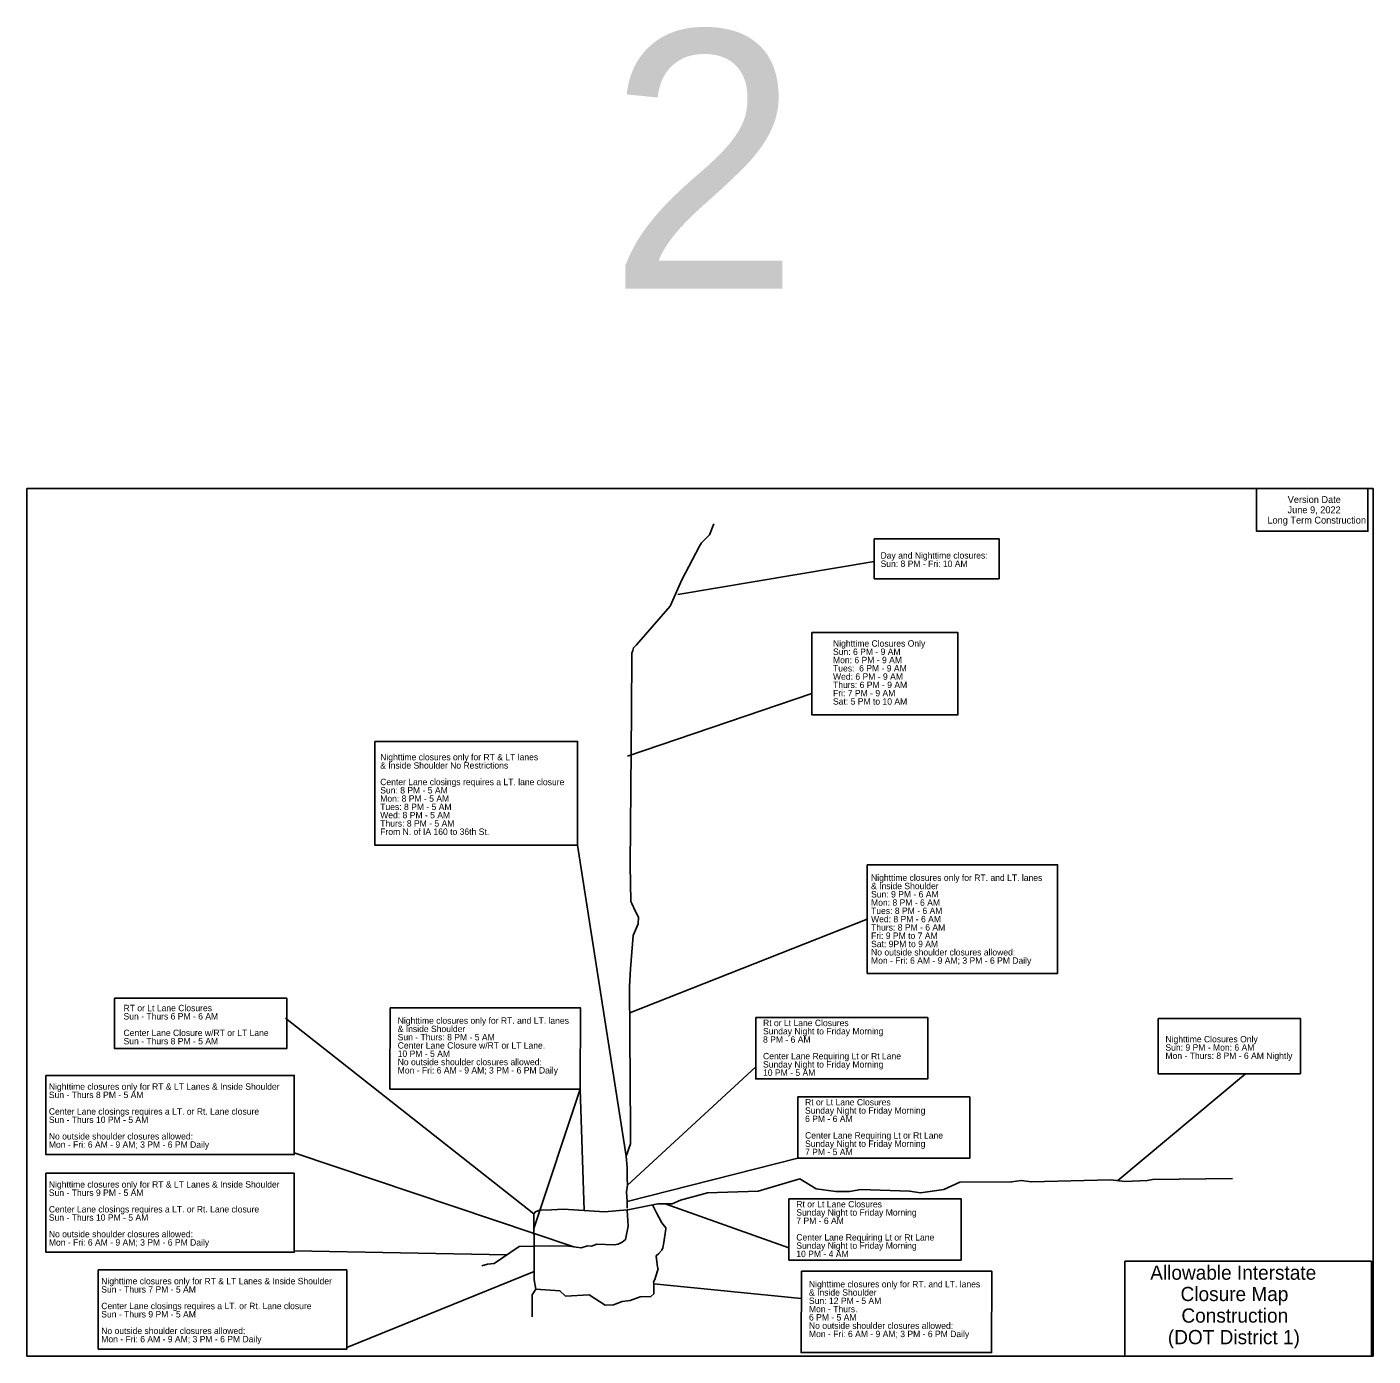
# Model space of a CAD drawing. Extents: x 10133 to 81668, y 7924 to 11018.
# Drawn here: x 13733 to 16868, y 7924 to 11018 of the extents above; entities that cross this region are included whole.
import ezdxf

# ---------------------------------------------------------------- set-up
doc = ezdxf.new("R2010")
doc.units = 0
for name, color, linetype in [('Level 1', 7, 'Continuous'), ('Level 10', 7, 'Continuous'), ('Level 12', 7, 'Continuous'), ('Level 4', 7, 'Continuous'), ('Level 5', 7, 'Continuous'), ('Level 6', 7, 'Continuous'), ('Level 63', 7, 'Continuous'), ('Level 7', 7, 'Continuous'), ('SheetAddendum', 7, 'Continuous'), ('SheetBorder', 7, 'Continuous'), ('SheetText', 7, 'Continuous')]:
    doc.layers.add(name, color=color, linetype=linetype)

msp = doc.modelspace()

# ---------------------------------------------------------------- linework, layer by layer
at = {"layer": 'Level 1'}
for p, q in [((16289.1, 8145), (16863.6, 8145)), ((16863.6, 8145), (16863.6, 7924)), ((16863.6, 7924), (16289.1, 7924))]:
    msp.add_line(p, q, dxfattribs=at)
msp.add_lwpolyline([(16289.1, 7924), (16289.1, 7924), (16289.1, 8145)], dxfattribs=at)
at = {"layer": 'Level 10'}
msp.add_line((15015, 9113.4), (15128.1, 8389.4), dxfattribs=at)
msp.add_lwpolyline([(14542.4, 9354.9), (15015, 9354.9), (15015, 9113.4), (14542.4, 9113.4)], close=True, dxfattribs=at)
for points in [[(15138.3, 8451.6), (15138.5, 8422.8), (15138.5, 8417.9), (15128.1, 8389.4)], [(15128.1, 8389.4), (15130.6, 8363.2), (15130.2, 8338.5)]]:
    msp.add_lwpolyline(points, dxfattribs=at)
at = {"layer": 'Level 12'}
msp.add_lwpolyline([(16596.1, 9944), (16855.7, 9944), (16855.7, 9844), (16596.1, 9844)], close=True, dxfattribs=at)
at = {"layer": 'Level 4'}
for p, q in [((15689.4, 8941.2), (15136.4, 8722.9)), ((15535.6, 8058.4), (15192.2, 8091.8))]:
    msp.add_line(p, q, dxfattribs=at)
for points in [[(15689.4, 9067.6), (16132.9, 9067.6), (16132.9, 8814.7), (15689.4, 8814.7)], [(15536.2, 8121.3), (15979.6, 8121.3), (15979.1, 7932), (15535.6, 7932)]]:
    msp.add_lwpolyline(points, close=True, dxfattribs=at)
for points in [[(15135.9, 8784.2), (15138.3, 8451.6)], [(14918, 8079.5), (14973.7, 8076.2), (14987.1, 8063.8), (15041.6, 8066.3), (15079.1, 8042.4), (15098.6, 8043.1), (15118.5, 8050.8), (15137.2, 8053), (15160.7, 8062.1), (15185.9, 8062.3), (15192.7, 8068.9), (15192.2, 8091.8), (15192.1, 8096.8), (15194.9, 8102.6), (15201.2, 8122.8), (15202.3, 8126.1), (15201.8, 8128.5), (15201.3, 8131.4), (15198.1, 8155.7), (15198.9, 8158.5), (15203.1, 8162.2), (15211.3, 8170.7), (15213.7, 8175.7), (15215.5, 8188.7), (15220.7, 8219.9), (15220.5, 8222.2), (15211.2, 8234), (15199.1, 8257.5), (15190.2, 8274.8)]]:
    msp.add_lwpolyline(points, dxfattribs=at)
at = {"layer": 'Level 5'}
for p, q in [((14334.6, 8710.8), (14913.1, 8255.4)), ((15429.7, 8597.7), (15131.5, 8322.2)), ((15021.2, 8545.6), (14913.3, 8221.3)), ((15030, 8262.9), (15021.2, 8545.6)), ((15006.2, 8178.3), (14355.2, 8396.8)), ((15130.2, 8283.7), (15527.6, 8384.6)), ((15507.1, 8175.7), (15218.6, 8278.4)), ((14849.9, 8159.3), (14355.2, 8169.1)), ((14914, 8120.7), (14477.2, 7944))]:
    msp.add_line(p, q, dxfattribs=at)
for points in [[(13936.8, 8757.1), (14337.5, 8757.1), (14337.5, 8639.8), (13936.8, 8639.8)], [(14578.3, 8734.9), (15021.7, 8734.9), (15021.2, 8545.6), (14577.7, 8545.6)], [(15429.7, 8712), (15830.5, 8712), (15830.5, 8569.2), (15429.7, 8569.2)], [(13776.7, 8577.3), (14355.2, 8577.3), (14355.2, 8393.1), (13776.7, 8393.1)], [(15527.6, 8527.4), (15928.4, 8527.4), (15928.4, 8384.6), (15527.6, 8384.6)], [(13776.7, 8349.6), (14355.2, 8349.6), (14355.2, 8165.5), (13776.7, 8165.5)], [(15507.1, 8290.1), (15907.9, 8290.1), (15907.9, 8147.3), (15507.1, 8147.3)], [(13898.8, 8124.5), (14477.2, 8124.5), (14477.2, 7940.3), (13898.8, 7940.3)]]:
    msp.add_lwpolyline(points, close=True, dxfattribs=at)
for points in [[(15128.5, 8306.3), (15131.5, 8322.2), (15130.2, 8338.5)], [(15128.5, 8306.3), (15130.2, 8283.7), (15130.2, 8268.7)], [(15131.9, 8264.5), (15135.9, 8264.9), (15202.2, 8278.2), (15234.9, 8278.6), (15254.6, 8286.8)], [(14913.3, 8234.1), (14913.1, 8255.4), (14916.7, 8259.7), (14926.3, 8263.4), (14954.2, 8264.8)], [(14913.6, 8179.6), (14988.9, 8180.3), (15023.5, 8176.3), (15038.1, 8180.4), (15047.7, 8180.1), (15059.6, 8184.4), (15100.3, 8182.7), (15109.7, 8184.6), (15119.1, 8189.3), (15126.7, 8195.2), (15132.6, 8226.5), (15130.2, 8263.7)], [(14954.2, 8264.8), (14982.1, 8266.2), (15077.9, 8259.6), (15130.7, 8264.4)], [(15130.7, 8264.4), (15131.9, 8264.5)], [(14913.6, 8179.3), (14913.3, 8234.1)], [(14792.1, 8134.4), (14805.3, 8137.6), (14820.8, 8139.4), (14878.9, 8179.2), (14913.6, 8179.6)], [(14909.4, 8015), (14909.4, 8066.8), (14918, 8079.5), (14914.1, 8101.5), (14913.6, 8176.5)], [(14913.6, 8179), (14913.6, 8179.3)], [(14913.6, 8176.5), (14913.6, 8179)]]:
    msp.add_lwpolyline(points, dxfattribs=at)
at = {"layer": 'Level 6'}
msp.add_line((15706, 9773.4), (15248.7, 9696.9), dxfattribs=at)
msp.add_lwpolyline([(15332.6, 9861.1), (15321.9, 9835.7), (15303.9, 9816.8), (15299.2, 9809.1), (15257.4, 9731.2), (15230.3, 9669.8), (15151.9, 9580), (15145.4, 9572.6), (15143.3, 9566.5), (15141.1, 9560.5), (15141.4, 9557.7), (15140.3, 9424)], dxfattribs=at)
msp.add_lwpolyline([(15706, 9826.6), (15996.6, 9826.6), (15996.6, 9733.5), (15706, 9733.5)], close=True, dxfattribs=at)
at = {"layer": 'Level 7'}
msp.add_line((16273, 8332.4), (16570.4, 8581.4), dxfattribs=at)
msp.add_lwpolyline([(16366.9, 8709.7), (16698.4, 8709.7), (16698.4, 8581.4), (16366.9, 8581.4)], close=True, dxfattribs=at)
for points in [[(15254.6, 8286.8), (15317.8, 8304), (15435.3, 8307.6), (15532.7, 8336.3), (15570.7, 8313.4), (15616.4, 8307.4), (15648.5, 8307.4), (15674.3, 8311.8)], [(15674.3, 8311.8), (15787.8, 8307.9), (15813.3, 8304.3), (15868.2, 8311.5), (15905.5, 8329.1), (16025.8, 8329.3), (16048.4, 8333.1), (16071, 8330), (16256.9, 8334.1), (16289.1, 8330.7), (16341.2, 8332.6), (16353.9, 8334.8), (16540.2, 8337.2)]]:
    msp.add_lwpolyline(points, dxfattribs=at)
at = {"layer": 'SheetAddendum'}
msp.add_line((15560.8, 9466.7), (15131.4, 9320.3), dxfattribs=at)
msp.add_lwpolyline([(15560.8, 9608.2), (15900.7, 9608.2), (15900.7, 9416.4), (15560.8, 9416.4)], close=True, dxfattribs=at)
for points in [[(15140.3, 9424), (15137.3, 9066.7)], [(15137.3, 9066.7), (15138.7, 8982.1), (15141, 8977.4), (15150, 8958.8), (15156.5, 8945.4), (15155.8, 8930), (15144.2, 8902.8), (15138.2, 8825.2), (15135.9, 8784.2)]]:
    msp.add_lwpolyline(points, dxfattribs=at)
at = {"layer": 'SheetBorder'}
msp.add_lwpolyline([(13732.5, 9944), (16867.5, 9944), (16867.5, 7924), (13732.5, 7924)], close=True, dxfattribs=at)

# ---------------------------------------------------------------- texts
at = {"layer": 'Level 10'}
for s, height, p in [('Nighttime closures only for RT & LT lanes ', 14.906, (14555.3, 9310.9)), ('& Inside Shoulder No Restrictions', 14.906, (14555.3, 9291.6)), ('Sun: 8 PM - 5 AM ', 14.906, (14555.3, 9233.7)), ('Center Lane closings requires a LT. lane closure', 14.906, (14555.3, 9253)), ('Mon: 8 PM - 5 AM', 14.906, (14555.3, 9214.4)), ('Wed: 8 PM - 5 AM', 14.906, (14555.3, 9175.9)), ('Tues: 8 PM - 5 AM', 14.906, (14555.3, 9195.1)), ('Thurs: 8 PM - 5 AM', 14.906, (14555.3, 9156.6)), ('From N. of IA 160 to 36th St.', 14.906, (14555.3, 9137.3)), ('Allowable Interstate', 33.124, (16348.6, 8101.7)), ('Closure Map', 33.124, (16419.2, 8052)), ('Construction', 33.124, (16421.2, 8001.8)), ('(DOT District 1)', 33.124, (16389.6, 7951.6))]:
    msp.add_text(s, height=height, dxfattribs=at).set_placement(p)
at = {"layer": 'Level 4'}
for s, p in [('Nighttime closures only for RT. and LT. lanes', (15698.4, 9030.2)), ('& Inside Shoulder', (15698.4, 9010.9)), ('Sun: 9 PM - 6 AM ', (15698.4, 8991.6)), ('Tues: 8 PM - 6 AM', (15698.4, 8953.1)), ('Mon: 8 PM - 6 AM', (15698.4, 8972.3)), ('Wed: 8 PM - 6 AM', (15698.4, 8933.8)), ('Thurs: 8 PM - 6 AM', (15698.4, 8914.5)), ('Fri: 9 PM to 7 AM', (15698.4, 8895.2)), ('Sat: 9PM to 9 AM', (15698.4, 8875.9)), ('No outside shoulder closures allowed: ', (15698.4, 8856.6)), ('Mon - Fri: 6 AM - 9 AM; 3 PM - 6 PM Daily', (15698.4, 8837.3)), ('Nighttime closures only for RT. and LT. lanes', (15553.8, 8083.9)), ('& Inside Shoulder', (15553.8, 8064.6)), ('Sun: 12 PM - 5 AM ', (15553.8, 8045.3)), ('Mon - Thurs.', (15553.8, 8026)), ('6 PM - 5 AM', (15553.8, 8006.7)), ('No outside shoulder closures allowed: ', (15553.8, 7987.4)), ('Mon - Fri: 6 AM - 9 AM; 3 PM - 6 PM Daily', (15553.8, 7968.1))]:
    msp.add_text(s, height=14.906, dxfattribs=at).set_placement(p)
at = {"layer": 'Level 5'}
for s, p in [('Sun - Thurs 6 PM - 6 AM', (13957.5, 8707.5)), ('RT or Lt Lane Closures', (13957.5, 8726.8)), ('Center Lane Closure w/RT or LT Lane', (13957.5, 8669)), ('& Inside Shoulder', (14596, 8678.2)), ('Nighttime closures only for RT. and LT. lanes', (14596, 8697.5)), ('Sunday Night to Friday Morning', (15446.8, 8672.8)), ('Rt or Lt Lane Closures', (15446.8, 8692.1)), ('Sun - Thurs 8 PM - 5 AM', (13957.5, 8649.7)), ('Sun - Thurs: 8 PM - 5 AM ', (14596, 8658.9)), ('Center Lane Closure w/RT or LT Lane.', (14596, 8639.7)), ('8 PM - 6 AM', (15446.8, 8653.5)), ('10 PM - 5 AM', (14596, 8620.4)), ('Center Lane Requiring Lt or Rt Lane', (15446.8, 8614.9)), ('No outside shoulder closures allowed: ', (14596, 8601.1)), ('Mon - Fri: 6 AM - 9 AM; 3 PM - 6 PM Daily', (14596, 8581.8)), ('Sunday Night to Friday Morning', (15446.8, 8595.6)), ('10 PM - 5 AM', (15446.8, 8576.4)), ('Nighttime closures only for RT & LT Lanes & Inside Shoulder', (13783.6, 8543.9)), ('Sun - Thurs 8 PM - 5 AM ', (13783.6, 8524.6)), ('Center Lane closings requires a LT. or Rt. Lane closure ', (13783.6, 8486)), ('Sunday Night to Friday Morning', (15544.7, 8488.2)), ('Rt or Lt Lane Closures', (15544.7, 8507.5)), ('Sun - Thurs 10 PM - 5 AM', (13783.6, 8466.7)), ('6 PM - 6 AM', (15544.7, 8468.9)), ('No outside shoulder closures allowed: ', (13783.6, 8428.2)), ('Center Lane Requiring Lt or Rt Lane', (15544.7, 8430.3)), ('Mon - Fri: 6 AM - 9 AM; 3 PM - 6 PM Daily', (13783.6, 8408.9)), ('Sunday Night to Friday Morning', (15544.7, 8411)), ('7 PM - 5 AM', (15544.7, 8391.7)), ('Sun - Thurs 9 PM - 5 AM ', (13783.6, 8296.9)), ('Nighttime closures only for RT & LT Lanes & Inside Shoulder', (13783.6, 8316.2)), ('Rt or Lt Lane Closures', (15524.3, 8270.1)), ('Sun - Thurs 10 PM - 5 AM', (13783.6, 8239.1)), ('Center Lane closings requires a LT. or Rt. Lane closure ', (13783.6, 8258.3)), ('Sunday Night to Friday Morning', (15524.3, 8250.9)), ('7 PM - 6 AM', (15524.3, 8231.6)), ('No outside shoulder closures allowed: ', (13783.6, 8200.5)), ('Mon - Fri: 6 AM - 9 AM; 3 PM - 6 PM Daily', (13783.6, 8181.2)), ('Sunday Night to Friday Morning', (15524.3, 8173.7)), ('Center Lane Requiring Lt or Rt Lane', (15524.3, 8193)), ('10 PM - 4 AM', (15524.3, 8154.4)), ('Nighttime closures only for RT & LT Lanes & Inside Shoulder', (13905.6, 8091.1)), ('Sun - Thurs 7 PM - 5 AM ', (13905.6, 8071.8)), ('Sun - Thurs 9 PM - 5 AM ', (13905.6, 8013.9)), ('Center Lane closings requires a LT. or Rt. Lane closure ', (13905.6, 8033.2)), ('No outside shoulder closures allowed: ', (13905.6, 7975.3)), ('Mon - Fri: 6 AM - 9 AM; 3 PM - 6 PM Daily', (13905.6, 7956))]:
    msp.add_text(s, height=14.906, dxfattribs=at).set_placement(p)
at = {"layer": 'Level 6'}
for s, p in [('Day and Nighttime closures:', (15720.5, 9780.4)), ('Sun: 8 PM - Fri: 10 AM', (15720.5, 9761.1))]:
    msp.add_text(s, height=14.906, dxfattribs=at).set_placement(p)
at = {"layer": 'Level 63'}
for s, p in [('Version Date', (16668.8, 9910)), ('Long Term Construction', (16621.5, 9862)), ('June 9, 2022', (16668.4, 9886))]:
    msp.add_text(s, height=16, dxfattribs=at).set_placement(p)
at = {"layer": 'Level 7'}
for s, p in [('Nighttime Closures Only', (16384, 8654.3)), ('Sun: 9 PM - Mon: 6 AM', (16384, 8635)), ('Mon - Thurs: 8 PM - 6 AM Nightly', (16384, 8615.7))]:
    msp.add_text(s, height=14.906, dxfattribs=at).set_placement(p)
at = {"layer": 'SheetAddendum'}
for s, p in [('Sun: 6 PM - 9 AM', (15609.8, 9556.2)), ('Nighttime Closures Only', (15609.8, 9575.5)), ('Tues:  6 PM - 9 AM ', (15609.8, 9517.7)), ('Mon: 6 PM - 9 AM ', (15609.8, 9536.9)), ('Wed: 6 PM - 9 AM ', (15609.8, 9498.4)), ('Thurs: 6 PM - 9 AM ', (15609.8, 9479.1)), ('Fri: 7 PM - 9 AM', (15609.8, 9459.8)), ('Sat: 5 PM to 10 AM', (15609.8, 9440.5))]:
    msp.add_text(s, height=14.906, dxfattribs=at).set_placement(p)
at = {"layer": 'SheetText'}
msp.add_text('2', height=600, dxfattribs=at).set_placement((15085.9, 10409.2))

doc.saveas('drawing.dxf')
